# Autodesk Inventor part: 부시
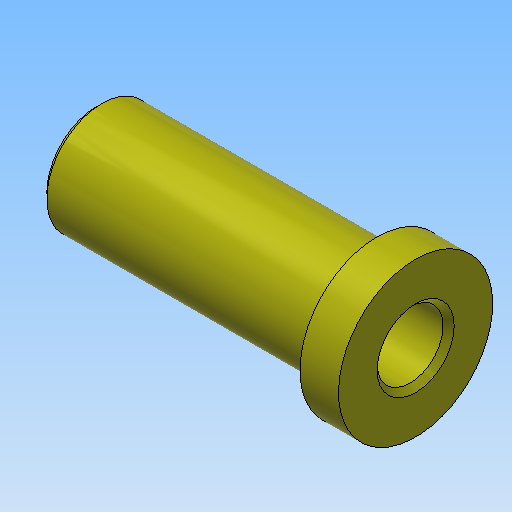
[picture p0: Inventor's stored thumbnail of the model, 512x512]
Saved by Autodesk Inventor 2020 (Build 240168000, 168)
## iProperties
Created: 2016-11
Part Number: 부시
Material: 강철, 연강
Document SubType Name: Modeling
Designer: mduedu
Density: 1 g/cm^3
Appearance: 노란색
Author: mduedu
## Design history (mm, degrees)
sketch "스케치1"
  geometry: L1 (0, 0)-(58, 0); L2 (58, 0)-(58, 14); L3 (58, 14)-(51, 14); L4 (51, 14)-(51, 10); L5 (51, 10)-(0, 10); L6 (0, 10)-(0, 0)
  constraints: 12 end point, 3 parallel, 2 perpendicular, 1 horizontal
  dimensions: "d0" = 58 distance of L1.start L1.end; "d1" = 7 distance of L2.end L3.end; "d2" = 28 diameter of L3 L1; "d3" = 20 diameter of L5 L1
revolve "회전1" sketch "스케치1" stored, may be unused: angle "d4" = 90 deg
hole "구멍1" diameter "d7" = 12; stored, may be unused: countersink angle "d11" = 90 deg, drill point angle "d13" = 118 deg; dims "d5" = 10, "d6" = 10, "d8" = 6, "d9" = 4, "d10" = 2, "d12" = 8
chamfer "모따기1" distance "d14" = 1; stored, may be unused: second distance "d15" = 2, angle "d16" = 45 deg
node "솔리드1"
